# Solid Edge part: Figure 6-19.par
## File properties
Author: CADCIM
Template: normal.par
Last saved by: Ashutosh-CADCIM
Revision: 9
Application: Solid Edge
Accuracy: 0.99
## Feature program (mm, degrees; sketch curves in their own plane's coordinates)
sketch for "unnamed Protrusion 1" plane through (0, 0, 0) normal (0, 0, 1) x-axis (1, 0, 0)
  line (-55, -37.5) -> (55, -37.5)
  line (55, -37.5) -> (55, 37.5)
  line (55, 37.5) -> (-55, 37.5)
  line (-55, 37.5) -> (-55, -37.5)
extrude "unnamed Protrusion 1" add finite 19.05 along +normal
sketch for "ExtrudedProtrusion_2" plane through (0, 0, 19.05) normal (0, 0, 1) x-axis (0, 1, 0)
  circle centre (-3.8876, -1.0799) radius 22.7058
extrude "ExtrudedProtrusion_2" add finite 41.275 along +normal
sketch for "ExtrudedProtrusion_3" plane through (-55, 0, 9.525) normal (-1, 0, 0) x-axis (0, -1, 0)
  line (29.4545, -9.525) -> (-29.4545, -9.525)
  line (-29.4545, -9.525) -> (-29.4545, 36.1246)
  line (-29.4545, 36.1246) -> (37.5, 36.1246)
  line (37.5, 36.1246) -> (37.5, -9.525)
extrude "ExtrudedProtrusion_3" add finite 15.875 along +normal
sketch for "ExtrudedProtrusion_4" plane through (-7.9375, 29.4545, 22.8248) normal (0, 1, 0) x-axis (0, 0, -1)
  line (22.8248, 62.9375) -> (22.8248, -62.9375)
  line (-35.4203, -62.9375) -> (22.8248, -62.9375)
  line (-35.4203, 62.9375) -> (-35.4203, -62.9375)
  line (-35.4203, 62.9375) -> (22.8248, 62.9375)
extrude "ExtrudedProtrusion_4" add finite 9.525 along +normal
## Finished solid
Body 1: solid body, 12 faces, 26 edges, 16 vertices.
  Faces by surface: plane 11, cylinder 1
  Edges by curve: line 24, circle 2
Bounding box of the edges (mm): 125.875 x 76.480 x 60.325, from (-70.875, -37.5, 0) to (55, 38.9795, 60.325).
Cylindrical faces by radius (mm): R22.7058 x1
Planar faces by outward normal: +x 2, +y 1, +z 4, -x 1, -y 2, -z 1
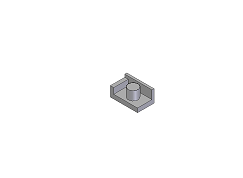
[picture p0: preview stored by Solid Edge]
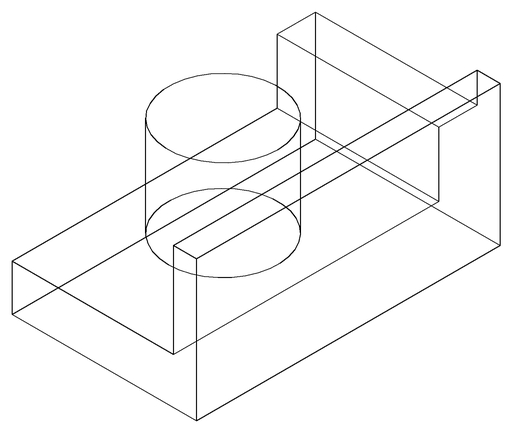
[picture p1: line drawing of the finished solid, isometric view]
